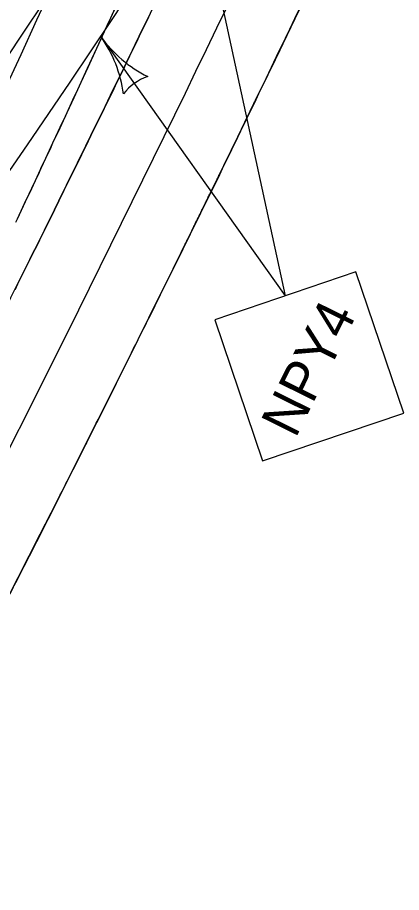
# Model space of a CAD drawing. Extents: x 14097936 to 14128734, y 8632000 to 8683104.
# Drawn here: x 14119720.1 to 14119789.7, y 8669688.3 to 8669846.7 of the extents above; entities that cross this region are included whole.
import ezdxf

# ---------------------------------------------------------------- set-up
doc = ezdxf.new("R2010")
doc.units = 0
for name, color, linetype in [('dsnPaintExistingBrokenLaneLineWhite', 7, 'Continuous'), ('dsnPaintExistingEdgeLineRightWhite', 7, 'Continuous'), ('dsnPaintExistingNoPassingYellow', 7, 'Continuous'), ('dsnPaintPlaceBrokenLaneWhite', 7, 'Continuous'), ('dsnPaintPlaceEdgeLineRightWhite', 7, 'Continuous'), ('dsnPaintPlaceNoPassingYellow', 7, 'Continuous'), ('dsnShadingPaved', 7, 'Continuous'), ('dsnStdLabel', 7, 'Continuous'), ('dsnTapeRemoveChannelizingLaneWhite', 7, 'Continuous'), ('dsnTapeRemoveChannelizingLaneYellow', 7, 'Continuous')]:
    doc.layers.add(name, color=color, linetype=linetype)

msp = doc.modelspace()

# ---------------------------------------------------------------- linework, layer by layer
at = {"layer": 'dsnPaintExistingBrokenLaneLineWhite'}
msp.add_arc((14115457.93, 8671918.7), 4772.49, 331.51238, 334.87343, dxfattribs=at)
at = {"layer": 'dsnPaintExistingEdgeLineRightWhite'}
for points in [[(14119753.42, 8669811.53), (14119753.42, 8669811.53), (14119753.42, 8669811.54), (14119753.42, 8669811.54), (14119753.42, 8669811.54)], [(14119753.42, 8669811.53), (14119753.42, 8669811.53), (14119753.42, 8669811.54), (14119753.42, 8669811.54), (14119753.42, 8669811.54)], [(14119722.32, 8669749.29), (14119722.32, 8669749.29), (14119722.32, 8669749.29), (14119722.33, 8669749.3), (14119722.33, 8669749.3)], [(14119722.32, 8669749.29), (14119722.32, 8669749.29), (14119722.32, 8669749.29), (14119722.33, 8669749.3), (14119722.33, 8669749.3)]]:
    msp.add_lwpolyline(points, dxfattribs=at)
msp.add_arc((14115457.93, 8671918.7), 4784.49, 331.51238, 334.87343, dxfattribs=at)
for points in [[(14119753.42, 8669811.54), (14119753.51, 8669811.71), (14119753.64, 8669811.97), (14119753.78, 8669812.28), (14119753.86, 8669812.43), (14119753.89, 8669812.5), (14119753.91, 8669812.54), (14119753.92, 8669812.56), (14119754.02, 8669812.76), (14119754.1, 8669812.93), (14119754.19, 8669813.11), (14119754.2, 8669813.12), (14119754.21, 8669813.15), (14119754.21, 8669813.16), (14119754.23, 8669813.18), (14119754.23, 8669813.19), (14119754.24, 8669813.21), (14119754.25, 8669813.22), (14119754.27, 8669813.28), (14119754.29, 8669813.32), (14119754.36, 8669813.45), (14119754.4, 8669813.54), (14119754.78, 8669814.32), (14119755.12, 8669815.01), (14119756.15, 8669817.1), (14119756.83, 8669818.49), (14119758.87, 8669822.67), (14119762.94, 8669831.03), (14119766.98, 8669839.4), (14119769.67, 8669844.98)], [(14119753.42, 8669811.54), (14119753.51, 8669811.71), (14119753.64, 8669811.97), (14119753.78, 8669812.28), (14119753.86, 8669812.43), (14119753.89, 8669812.5), (14119753.91, 8669812.54), (14119753.92, 8669812.56), (14119754.02, 8669812.76), (14119754.1, 8669812.93), (14119754.19, 8669813.11), (14119754.2, 8669813.12), (14119754.21, 8669813.15), (14119754.21, 8669813.16), (14119754.23, 8669813.18), (14119754.23, 8669813.19), (14119754.24, 8669813.21), (14119754.25, 8669813.22), (14119754.27, 8669813.28), (14119754.29, 8669813.32), (14119754.36, 8669813.45), (14119754.4, 8669813.54), (14119754.78, 8669814.32), (14119755.12, 8669815.01), (14119756.15, 8669817.1), (14119756.83, 8669818.49), (14119758.87, 8669822.67), (14119762.94, 8669831.03), (14119766.98, 8669839.4), (14119769.67, 8669844.98)], [(14119722.33, 8669749.3), (14119722.41, 8669749.46), (14119722.53, 8669749.7), (14119722.68, 8669749.98), (14119722.74, 8669750.11), (14119722.78, 8669750.19), (14119722.8, 8669750.23), (14119722.9, 8669750.43), (14119722.98, 8669750.59), (14119723.08, 8669750.79), (14119723.1, 8669750.83), (14119723.14, 8669750.89), (14119723.15, 8669750.91), (14119723.16, 8669750.94), (14119723.17, 8669750.96), (14119723.18, 8669750.97), (14119723.18, 8669750.98), (14119723.18, 8669750.99), (14119723.23, 8669751.07), (14119723.27, 8669751.15), (14119723.64, 8669751.88), (14119723.97, 8669752.53), (14119724.95, 8669754.46), (14119725.61, 8669755.76), (14119727.57, 8669759.64), (14119731.49, 8669767.4), (14119738, 8669780.35), (14119744.45, 8669793.33), (14119748.3, 8669801.13), (14119750.22, 8669805.03), (14119750.86, 8669806.33), (14119751.82, 8669808.29), (14119752.14, 8669808.94), (14119752.78, 8669810.24), (14119753.1, 8669810.88), (14119753.42, 8669811.53)], [(14119722.33, 8669749.3), (14119722.41, 8669749.46), (14119722.53, 8669749.7), (14119722.68, 8669749.98), (14119722.74, 8669750.11), (14119722.78, 8669750.19), (14119722.8, 8669750.23), (14119722.9, 8669750.43), (14119722.98, 8669750.59), (14119723.08, 8669750.79), (14119723.1, 8669750.83), (14119723.14, 8669750.89), (14119723.15, 8669750.91), (14119723.16, 8669750.94), (14119723.17, 8669750.96), (14119723.18, 8669750.97), (14119723.18, 8669750.98), (14119723.18, 8669750.99), (14119723.23, 8669751.07), (14119723.27, 8669751.15), (14119723.64, 8669751.88), (14119723.97, 8669752.53), (14119724.95, 8669754.46), (14119725.61, 8669755.76), (14119727.57, 8669759.64), (14119731.49, 8669767.4), (14119738, 8669780.35), (14119744.45, 8669793.33), (14119748.3, 8669801.13), (14119750.22, 8669805.03), (14119750.86, 8669806.33), (14119751.82, 8669808.29), (14119752.14, 8669808.94), (14119752.78, 8669810.24), (14119753.1, 8669810.88), (14119753.42, 8669811.53)], [(14119690.33, 8669687.52), (14119690.42, 8669687.68), (14119690.54, 8669687.92), (14119690.69, 8669688.2), (14119690.75, 8669688.32), (14119690.8, 8669688.4), (14119690.82, 8669688.44), (14119690.92, 8669688.64), (14119691.01, 8669688.8), (14119691.11, 8669689), (14119691.13, 8669689.04), (14119691.17, 8669689.1), (14119691.18, 8669689.12), (14119691.19, 8669689.15), (14119691.2, 8669689.17), (14119691.21, 8669689.18), (14119691.21, 8669689.19), (14119691.22, 8669689.2), (14119691.26, 8669689.29), (14119691.3, 8669689.37), (14119691.68, 8669690.09), (14119692.02, 8669690.73), (14119693.03, 8669692.65), (14119693.71, 8669693.93), (14119695.73, 8669697.78), (14119699.76, 8669705.49), (14119706.45, 8669718.35), (14119713.09, 8669731.23), (14119717.06, 8669738.97), (14119719.03, 8669742.84), (14119719.69, 8669744.13), (14119720.68, 8669746.07), (14119721.01, 8669746.71), (14119721.67, 8669748), (14119721.99, 8669748.65), (14119722.32, 8669749.29)], [(14119690.33, 8669687.52), (14119690.42, 8669687.68), (14119690.54, 8669687.92), (14119690.69, 8669688.2), (14119690.75, 8669688.32), (14119690.8, 8669688.4), (14119690.82, 8669688.44), (14119690.92, 8669688.64), (14119691.01, 8669688.8), (14119691.11, 8669689), (14119691.13, 8669689.04), (14119691.17, 8669689.1), (14119691.18, 8669689.12), (14119691.19, 8669689.15), (14119691.2, 8669689.17), (14119691.21, 8669689.18), (14119691.21, 8669689.19), (14119691.22, 8669689.2), (14119691.26, 8669689.29), (14119691.3, 8669689.37), (14119691.68, 8669690.09), (14119692.02, 8669690.73), (14119693.03, 8669692.65), (14119693.71, 8669693.93), (14119695.73, 8669697.78), (14119699.76, 8669705.49), (14119706.45, 8669718.35), (14119713.09, 8669731.23), (14119717.06, 8669738.97), (14119719.03, 8669742.84), (14119719.69, 8669744.13), (14119720.68, 8669746.07), (14119721.01, 8669746.71), (14119721.67, 8669748), (14119721.99, 8669748.65), (14119722.32, 8669749.29)]]:
    msp.add_open_spline(points, degree=3, dxfattribs=at)
at = {"layer": 'dsnPaintExistingNoPassingYellow'}
msp.add_arc((14115457.93, 8671918.7), 4760.49, 331.51238, 334.1332, dxfattribs=at)
at = {"layer": 'dsnPaintPlaceBrokenLaneWhite'}
msp.add_arc((14115416.69, 8671831.7), 4742.58, 334.09122, 339.391, dxfattribs=at)
at = {"layer": 'dsnPaintPlaceEdgeLineRightWhite'}
msp.add_arc((14115464.82, 8671807.98), 4676.93, 333.43454, 336.83378, dxfattribs=at)
at = {"layer": 'dsnPaintPlaceNoPassingYellow'}
for centre, radius, start, end in [((14115456.71, 8671919.32), 4761.86, 334.13293, 337.35837), ((14115416.69, 8671831.7), 4754.58, 334.83917, 337.17562)]:
    msp.add_arc(centre, radius, start, end, dxfattribs=at)
at = {"layer": 'dsnShadingPaved'}
for points in [[(14119771.98, 8669849.81), (14119770.36, 8669846.43), (14119769.81, 8669845.29), (14119769.62, 8669844.89), (14119768.18, 8669841.89), (14119767.64, 8669840.77), (14119765.99, 8669837.37), (14119765.56, 8669836.47), (14119765.46, 8669836.26), (14119763.8, 8669832.84), (14119763.27, 8669831.74), (14119761.61, 8669828.31), (14119761.48, 8669828.05), (14119761.09, 8669827.23), (14119759.41, 8669823.79), (14119758.89, 8669822.73), (14119757.39, 8669819.64), (14119757.21, 8669819.27), (14119756.69, 8669818.22), (14119755, 8669814.75), (14119754.49, 8669813.72), (14119753.28, 8669811.24), (14119752.78, 8669810.24), (14119752.28, 8669809.22), (14119750.57, 8669805.73), (14119750.07, 8669804.72), (14119749.15, 8669802.85), (14119748.34, 8669801.22), (14119747.85, 8669800.23), (14119746.12, 8669796.71), (14119745.63, 8669795.73), (14119745, 8669794.46), (14119744.56, 8669793.57), (14119743.88, 8669792.2), (14119743.41, 8669791.24), (14119741.65, 8669787.7), (14119741.17, 8669786.76), (14119740.84, 8669786.08), (14119739.4, 8669783.2), (14119738.94, 8669782.27), (14119737.16, 8669778.7), (14119736.66, 8669777.71), (14119734.91, 8669774.21), (14119734.45, 8669773.3), (14119732.65, 8669769.71), (14119732.47, 8669769.36), (14119732.2, 8669768.82), (14119730.39, 8669765.22), (14119729.95, 8669764.35), (14119728.26, 8669761.01), (14119728.12, 8669760.73), (14119727.69, 8669759.87), (14119725.85, 8669756.25), (14119725.42, 8669755.4), (14119724.04, 8669752.66), (14119723.58, 8669751.76), (14119723.16, 8669750.93), (14119721.3, 8669747.28), (14119720.88, 8669746.46), (14119719.79, 8669744.33)], [(14119719.86, 8669809.64), (14119720.14, 8669810.24), (14119721.98, 8669814.16), (14119722.27, 8669814.77), (14119722.75, 8669815.8), (14119724.1, 8669818.69), (14119724.39, 8669819.32), (14119726.21, 8669823.22), (14119726.51, 8669823.86), (14119726.68, 8669824.23), (14119728.32, 8669827.75), (14119728.63, 8669828.4), (14119730.43, 8669832.28), (14119730.74, 8669832.95), (14119732.53, 8669836.82), (14119732.84, 8669837.5), (14119734.5, 8669841.09), (14119734.62, 8669841.36), (14119734.94, 8669842.05), (14119736.71, 8669845.89), (14119737.04, 8669846.6), (14119738.38, 8669849.54)], [(14119719.86, 8669809.64), (14119720.14, 8669810.24), (14119721.98, 8669814.16), (14119722.27, 8669814.77), (14119722.75, 8669815.8), (14119724.1, 8669818.69), (14119724.39, 8669819.32), (14119726.21, 8669823.22), (14119726.51, 8669823.86), (14119726.68, 8669824.23), (14119728.32, 8669827.75), (14119728.63, 8669828.4), (14119730.43, 8669832.28), (14119730.74, 8669832.95), (14119732.53, 8669836.82), (14119732.84, 8669837.5), (14119734.5, 8669841.09), (14119734.62, 8669841.36), (14119734.94, 8669842.05), (14119736.71, 8669845.89), (14119737.04, 8669846.6), (14119738.38, 8669849.54)], [(14119719.69, 8669797.45), (14119720.16, 8669798.39), (14119721.91, 8669801.92), (14119722.38, 8669802.87), (14119723.06, 8669804.23), (14119723.5, 8669805.12), (14119724.12, 8669806.38), (14119724.6, 8669807.35), (14119726.34, 8669810.86), (14119726.82, 8669811.84), (14119727.62, 8669813.46), (14119728.54, 8669815.33), (14119729.03, 8669816.32), (14119730.74, 8669819.8), (14119731.24, 8669820.81), (14119731.73, 8669821.81), (14119732.94, 8669824.28), (14119733.44, 8669825.31), (14119735.13, 8669828.76), (14119735.64, 8669829.8), (14119735.82, 8669830.17), (14119737.32, 8669833.24), (14119737.83, 8669834.3), (14119739.5, 8669837.73), (14119739.9, 8669838.54), (14119740.02, 8669838.8), (14119741.68, 8669842.22), (14119742.2, 8669843.3), (14119743.85, 8669846.71)], [(14119743.85, 8669846.71), (14119742.2, 8669843.3), (14119741.68, 8669842.22), (14119740.02, 8669838.8), (14119739.9, 8669838.54), (14119739.5, 8669837.73), (14119737.83, 8669834.3), (14119737.32, 8669833.24), (14119735.82, 8669830.17), (14119735.64, 8669829.8), (14119735.13, 8669828.76), (14119733.44, 8669825.31), (14119732.94, 8669824.28), (14119731.73, 8669821.81), (14119731.24, 8669820.81), (14119730.74, 8669819.8), (14119729.03, 8669816.32), (14119728.54, 8669815.33), (14119727.62, 8669813.46), (14119726.82, 8669811.84), (14119726.34, 8669810.86), (14119724.6, 8669807.35), (14119724.12, 8669806.38), (14119723.5, 8669805.12), (14119723.06, 8669804.23), (14119722.38, 8669802.87), (14119721.91, 8669801.92), (14119720.16, 8669798.39), (14119719.69, 8669797.45)]]:
    msp.add_lwpolyline(points, dxfattribs=at)
at = {"layer": 'dsnStdLabel'}
for p in [(14119753.39, 8669866.49), (14119735.26, 8669843.2)]:
    msp.add_line(p, (14119768.64, 8669796.3), dxfattribs=at)
msp.add_lwpolyline([(14119764.5, 8669766.4), (14119790.08, 8669775.05), (14119781.42, 8669800.62), (14119755.85, 8669791.97)], close=True, dxfattribs=at)
for centre, radius, start, end in [((14119716.56, 8669829.89), 22.95, 7.3695, 35.4408), ((14119753.95, 8669856.51), 22.95, 215.4406, 243.5119), ((14119746.41, 8669827.52), 8.86, 107.7065, 143.1749)]:
    msp.add_arc(centre, radius, start, end, dxfattribs=at)
at = {"layer": 'dsnTapeRemoveChannelizingLaneWhite'}
for centre, radius, start, end in [((14118559.34, 8670625.19), 1412.15, 319.58068, 337.35767), ((14118856.61, 8670357.32), 988, 327.62991, 336.79664)]:
    msp.add_arc(centre, radius, start, end, dxfattribs=at)
at = {"layer": 'dsnTapeRemoveChannelizingLaneYellow'}
for centre, radius, start, end in [((14118559.34, 8670625.19), 1400.15, 321.68516, 337.35766), ((14118856.5, 8670357.19), 1000, 323.53736, 337.142)]:
    msp.add_arc(centre, radius, start, end, dxfattribs=at)

# ---------------------------------------------------------------- texts
at = {"layer": 'dsnStdLabel'}
msp.add_text('NPY4', height=7.2, rotation=63.6912, dxfattribs=at).set_placement((14119770.47, 8669770.35))

doc.saveas('drawing.dxf')
